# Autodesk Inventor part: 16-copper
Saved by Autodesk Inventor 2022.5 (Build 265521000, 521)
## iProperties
Created: 2025-02
Part Number: 16-copper
Material: Generic
Document SubType Name: Modeling
Designer: AdminForWorker
Density: 1 g/cm^3
Appearance: Default
Title: 16-copper
Author: AdminForWorker
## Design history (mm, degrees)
feature "Body1"
feature "Body3"
feature "Body2"
body "Solid1"
body "Solid2"
body "Solid3"
